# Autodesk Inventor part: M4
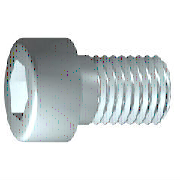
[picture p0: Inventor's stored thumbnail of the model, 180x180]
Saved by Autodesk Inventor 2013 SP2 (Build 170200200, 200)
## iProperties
IsCustomPart: 0
Company: 한국ATC센터
Created: 2014-10
Part Number: M4
Material: Steel, Mild
Description: 6각머리 태핑 나사
Document SubType Name: Modeling
Standard: KS B 1003
Designer: KYOUNG IL JANG
Standards Organization: KS
Language: ko-KR
Size Designation: M 4 x 10
Categories: <MemberInstance><Categories><Category DisplayName="조임쇠" InternalName="e4da775c-781d-43d5-af7c-5136215cf5a6" Mnemonic="FSTN"><Category DisplayName="볼트" InternalN
Density: 7.86 g/cm^3
Mass: 2.0371 g
Surface Area: 3.0572 cm^2
Volume: 0.259174 cm^3
Author: KYOUNG IL JANG
Revision Number: 1
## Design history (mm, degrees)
sketch "스케치1"
  geometry: L1 (-1, 0)-(10, 0); L2 (10, 0)-(10, 2); L3 (10, 2)-(1.75, 2); L4 (1.75, 2)-(1.32, 2); L5 (1.32, 2)-(0, 2); L6 (0, 2)-(0, 3.5); L7 (0, 3.5)-(-4, 3.5); L8 (-4, 3.5)-(-4, 1.732); L9 (-4, 1.732)-(-2, 1.732); L10 (-2, 1.732)-(-1, 0); L11 (-6.8, 0)-(12.8, 0) reference; L12 (0, -0.7)-(0, 4.2) reference; L13 (1.75, 2)-(0, 2)
  constraints: 22 end point, 6 parallel, 2 collinear, 2 perpendicular, 1 horizontal, 1 point on line
  dimensions: "d1" = 8.25 distance from line of L3.end L2 (= GEL); "d2" = 0.42952 distance of L4.end L3.end (computed from GAL); "d3" = 4 distance between parallel lines of L8 L6 (= KOH); "d4" = 2 distance of L8.end L9.end (= INTI); "d5" = 60 deg angle of L10 L1; "d6" = 4 diameter of L3 L1 (= GD); "d7" = 4 diameter of L5 L1 (= BDM); "d8" = 3.4641 diameter of L9 L1 (= 1.1547 x SW); "d9" = 7 diameter of L7 L1 (= KOD); "d26" = 10 distance between parallel lines of L12 L2 (= NLG)
revolve "본체" sketch "스케치1" stored, may be unused: angle "d10" = 90 deg
sketch "스케치2"
  geometry: L1 (0, -4.9)-(0, 4.9) reference; L2 (-4.9, 0)-(4.9, 0) reference; L3 (1.732, 0)-(0.866, -1.5); L4 (0.866, -1.5)-(-0.866, -1.5); L5 (-0.866, -1.5)-(-1.732, 0); L6 (-1.732, 0)-(-0.866, 1.5); L7 (-0.866, 1.5)-(0.866, 1.5); L8 (0.866, 1.5)-(1.732, 0); 2 further points
  constraints: 12 end point, 1 coincident, 1 horizontal alignment, 1 point on line, 12 other
extrude "슬롯" join sketch "스케치2" stored distance "d11" = 10; taper "d12" = 0 deg
workplane "Work Plane1"
fillet "Fillet2" dims "d30" = 0.1 (= R)
body "Solid1"
fillet "모깎기1" dims "d17" = 0.4 (= RR)
feature "스레드" dims "d13" = 8.25 (= GEL), "d14" = 0
chamfer "모따기1" distance "d15" = 0.42941 (= -0.5 x SPD + 0.5 x GD); stored, may be unused: second distance "d16" = 0.42941 (= GUL), angle "d27" = 45 deg
other parameters: "GD" = 4 (= NND) [user parameter; used in 2 equation terms], "NLG" = 10 [user parameter; used in 1 equation term], "GEL" = 8.25 [user parameter; used in 2 equation terms], "KOD" = 7 [user parameter; used in 1 equation term], "KOH" = 4 [user parameter; used in 1 equation term], "INTI" = 2 [user parameter; used in 1 equation term], "GAL" = 0.42941 (= 0.61345 x PTC) [user parameter; used in 1 equation term], "GUL" = 0.42941 (= 0.61345 x PTC) [user parameter; used in 1 equation term], "BDM" = 4 (= NND) [user parameter; used in 1 equation term], "SW" = 3 [user parameter; used in 2 equation terms], "RR" = 0.4 [user parameter; used in 1 equation term], "SPD" = 3.14117 (= NND - 1.2269 x PTC) [user parameter; used in 1 equation term], "d19" = 0, "d28" = 0, "d29" = 0, "R" = 0.1 [user parameter; used in 1 equation term], "PHH" = 0.2 [user parameter], "GD1" = 3.14117 (= THREADDIA - 1.2269 x PTC) [user parameter], "THREADDIA" = 4 [user parameter; used in 1 equation term], "FAWI" = 45 deg [user parameter], "TPU" = 14.28571 (computed from PTC) [user parameter], "PTC" = 0.7 [user parameter; used in 5 equation terms], "NND" = 4 [user parameter; used in 3 equation terms], "TOA" = 30 deg [user parameter], "E0" = 3.465 (= 1.155 x SW) [user parameter]
